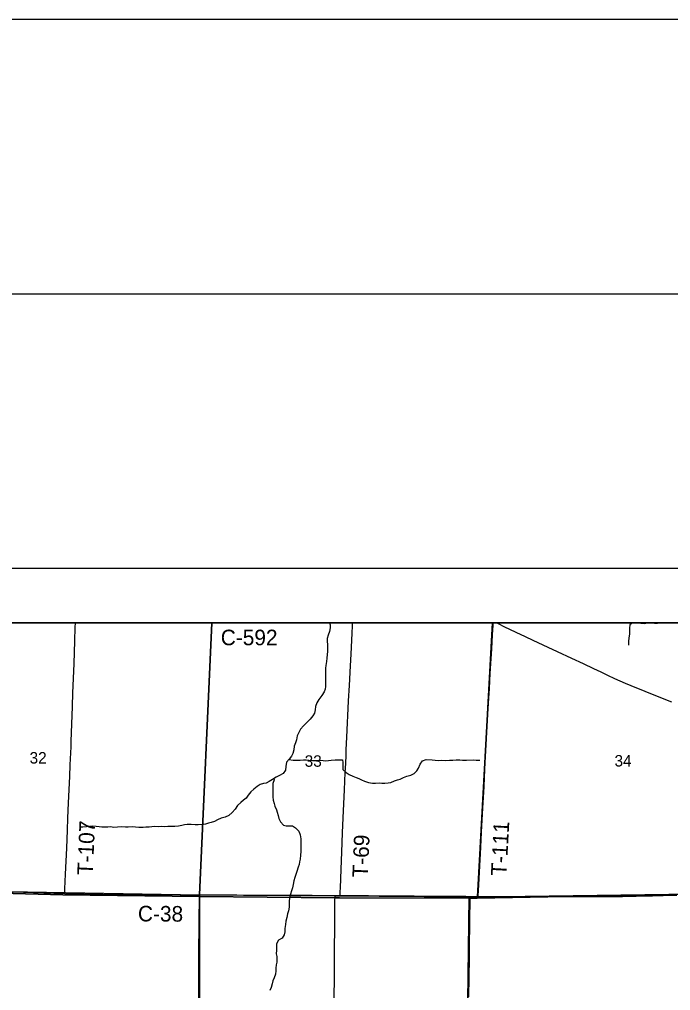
# Model space of a CAD drawing. Extents: x 0 to 34, y 0 to 22.
# Drawn here: x 3.165 to 4.352, y 20.23 to 22 of the extents above; entities that cross this region are included whole.
import ezdxf

# ---------------------------------------------------------------- set-up
doc = ezdxf.new("R2010")
doc.units = 0
for name, color, linetype in [('GM_X_County', 7, 'Continuous'), ('GM_X_County_Road', 7, 'Continuous'), ('GM_X_County_Road_Text', 7, 'Continuous'), ('GM_X_Minor_River', 7, 'Continuous'), ('GM_X_Section', 7, 'Continuous'), ('GM_X_Section_Text', 7, 'Continuous'), ('GM_X_Township', 7, 'Continuous'), ('GM_X_Township_Road', 7, 'Continuous'), ('GM_X_Township_Road_Text', 7, 'Continuous'), ('SH_Border', 7, 'Continuous'), ('SH_Cut_Line', 7, 'Continuous'), ('SH_Data', 7, 'Continuous')]:
    doc.layers.add(name, color=color, linetype=linetype)

msp = doc.modelspace()

# ---------------------------------------------------------------- linework, layer by layer
at = {"layer": 'GM_X_County'}
msp.add_lwpolyline([(9.4, 14.3965), (9.4, 20.9), (2.6, 20.9), (2.6, 14.4092)], dxfattribs=at)
at = {"layer": 'GM_X_County_Road'}
for points in [[(4.3542, 20.7556), (4.3253, 20.7671), (4.3057, 20.7749), (4.2803, 20.7852), (4.2695, 20.7898), (4.2504, 20.7983), (4.2375, 20.8044), (4.2254, 20.8101), (4.2122, 20.8162), (4.193, 20.8252), (4.1717, 20.8353), (4.146, 20.8472), (4.1291, 20.8551), (4.1013, 20.8682), (4.0872, 20.8748), (4.0703, 20.8827), (4.0487, 20.893), (4.0393, 20.8974), (4.0342, 20.9)], [(2.9957, 20.4134), (3.0058, 20.4131), (3.0244, 20.4127), (3.0421, 20.4123), (3.0896, 20.411), (3.1148, 20.4104), (3.1729, 20.4089), (3.2279, 20.4074), (3.2478, 20.4069)], [(3.2478, 20.4069), (3.2832, 20.4061), (3.3174, 20.4057), (3.3622, 20.4052), (3.3858, 20.405), (3.4175, 20.4048), (3.4461, 20.4047), (3.4585, 20.4046), (3.4744, 20.4046), (3.4932, 20.4045)], [(3.4932, 20.4045), (3.5045, 20.4044), (3.5303, 20.4042), (3.5481, 20.4041), (3.5617, 20.404), (3.5735, 20.4039), (3.585, 20.4038), (3.6077, 20.4038), (3.6494, 20.4036), (3.6758, 20.4034), (3.6985, 20.4034), (3.7094, 20.4033), (3.7196, 20.4032), (3.728, 20.4031), (3.7404, 20.4031)], [(3.7404, 20.4031), (3.7499, 20.4031)], [(3.7499, 20.4031), (3.7622, 20.4031), (3.7889, 20.4028), (3.8014, 20.4028), (3.8194, 20.4026), (3.8495, 20.4025), (3.8663, 20.4023), (3.8846, 20.4022), (3.9083, 20.4021), (3.9543, 20.4017), (3.9785, 20.4016), (3.9866, 20.4015)], [(3.9866, 20.4015), (3.9928, 20.4015), (4.001, 20.4014)], [(4.001, 20.4014), (4.0028, 20.4014), (4.0152, 20.4014), (4.0435, 20.4013), (4.0531, 20.4012), (4.0649, 20.4012), (4.0848, 20.4011), (4.0917, 20.4011), (4.1041, 20.4013), (4.1181, 20.4012), (4.1321, 20.4012), (4.1442, 20.4012), (4.1647, 20.4011), (4.1818, 20.4012), (4.1908, 20.4012), (4.2007, 20.4013), (4.2259, 20.4014), (4.2645, 20.4015), (4.2735, 20.4017), (4.289, 20.4019), (4.3192, 20.4026), (4.3381, 20.4032), (4.3633, 20.4039)]]:
    msp.add_lwpolyline(points, dxfattribs=at)
at = {"layer": 'GM_X_Minor_River'}
for points in [[(3.7303, 20.9), (3.7313, 20.8965), (3.7314, 20.8908), (3.7304, 20.8845), (3.7278, 20.8779), (3.7262, 20.8713), (3.726, 20.8658), (3.7264, 20.8607), (3.7269, 20.854), (3.7265, 20.848), (3.7261, 20.8423), (3.7255, 20.8356), (3.7247, 20.8294), (3.7234, 20.8224), (3.723, 20.8174), (3.7229, 20.8121), (3.7231, 20.8055), (3.7231, 20.8002), (3.7232, 20.7954), (3.723, 20.7905), (3.723, 20.7839), (3.7224, 20.7791), (3.7207, 20.7742), (3.7163, 20.7674), (3.7111, 20.7602), (3.7075, 20.754), (3.705, 20.7474), (3.7044, 20.7417), (3.7029, 20.7356), (3.7002, 20.7307), (3.6949, 20.7245), (3.6892, 20.7184), (3.6829, 20.7126), (3.6777, 20.7063), (3.6747, 20.7001), (3.6714, 20.694), (3.6699, 20.6868), (3.6684, 20.6812), (3.6661, 20.6753), (3.6653, 20.6688), (3.6635, 20.6622), (3.661, 20.6573), (3.6567, 20.6518), (3.6519, 20.646), (3.6509, 20.6382), (3.6499, 20.6317), (3.6457, 20.6253), (3.6395, 20.6217), (3.6332, 20.6185), (3.6262, 20.6144), (3.6203, 20.6106), (3.615, 20.6078), (3.6102, 20.6073), (3.604, 20.6054), (3.5985, 20.602), (3.5922, 20.5969), (3.5871, 20.5922), (3.5823, 20.5858), (3.5785, 20.5807), (3.5735, 20.5767), (3.5686, 20.5726), (3.5629, 20.5669), (3.5583, 20.5605), (3.553, 20.5542), (3.5469, 20.5488), (3.54, 20.5456), (3.5332, 20.5443), (3.5264, 20.5411), (3.5209, 20.5379), (3.5148, 20.536), (3.5099, 20.5349), (3.5046, 20.5332), (3.4983, 20.5327), (3.4913, 20.532), (3.4854, 20.5318), (3.478, 20.5326), (3.4712, 20.5326), (3.4661, 20.5319), (3.4612, 20.5308), (3.4553, 20.5295), (3.4483, 20.5288), (3.4426, 20.529), (3.436, 20.529), (3.4299, 20.5285), (3.4248, 20.5287), (3.4183, 20.5285), (3.4113, 20.5287), (3.4018, 20.5276), (3.3954, 20.5275), (3.3907, 20.5269), (3.3829, 20.527), (3.377, 20.5276), (3.3706, 20.5282), (3.3634, 20.5278), (3.3584, 20.5277)], [(4.2827, 20.9), (4.2777, 20.8965), (4.2769, 20.8905), (4.2773, 20.8844), (4.277, 20.8793), (4.2759, 20.8725), (4.2752, 20.8658), (4.2752, 20.8592)], [(4.3289, 20.9), (4.3277, 20.8991), (4.3228, 20.8991), (4.3158, 20.8999), (4.3096, 20.8992), (4.3044, 20.8985), (4.2976, 20.8989), (4.2902, 20.8997), (4.285, 20.9)], [(3.6563, 20.6514), (3.6565, 20.6512), (3.6639, 20.6499), (3.6701, 20.6497), (3.6766, 20.6498), (3.683, 20.6505), (3.6877, 20.6505), (3.6928, 20.6499), (3.6991, 20.6491), (3.7061, 20.6491), (3.711, 20.6498), (3.7188, 20.6489), (3.7237, 20.6488), (3.7288, 20.6494), (3.7336, 20.6497), (3.7406, 20.6503), (3.7476, 20.6506), (3.7541, 20.6502), (3.7546, 20.6453), (3.7544, 20.639), (3.7547, 20.6326), (3.7604, 20.627), (3.7661, 20.6236), (3.7727, 20.6207), (3.7787, 20.6182), (3.784, 20.6161), (3.7889, 20.6138), (3.7939, 20.6113), (3.8011, 20.6088), (3.8086, 20.6078), (3.8141, 20.6078), (3.8206, 20.6085), (3.8259, 20.6081), (3.8314, 20.6079), (3.8371, 20.6083), (3.8418, 20.609), (3.8486, 20.612), (3.8543, 20.6137), (3.8591, 20.615), (3.865, 20.618), (3.8714, 20.6206), (3.8786, 20.6223), (3.8849, 20.6257), (3.8896, 20.6304), (3.8925, 20.6353), (3.8956, 20.6423), (3.9, 20.6488), (3.9064, 20.6508), (3.9176, 20.6501)], [(3.9176, 20.6501), (3.9284, 20.649), (3.9352, 20.6495), (3.9424, 20.6491), (3.9489, 20.6495), (3.9553, 20.65), (3.9612, 20.6503), (3.9678, 20.6501), (3.9727, 20.6497), (3.9797, 20.6498), (3.993, 20.6501), (3.9979, 20.6499), (4.0042, 20.6495)], [(3.629, 20.616), (3.6296, 20.6142), (3.6269, 20.6072), (3.6273, 20.6007), (3.6272, 20.5945), (3.6268, 20.589), (3.627, 20.5827), (3.6275, 20.5768), (3.6292, 20.5709), (3.6309, 20.5662), (3.6335, 20.5595), (3.6352, 20.5548), (3.6369, 20.5487), (3.638, 20.5436), (3.641, 20.5371), (3.6465, 20.5314), (3.6514, 20.5299), (3.6561, 20.5302), (3.6631, 20.5298), (3.6682, 20.5262), (3.6743, 20.5203), (3.6771, 20.5136), (3.6778, 20.5064), (3.6778, 20.4996), (3.678, 20.4931), (3.6783, 20.4882), (3.6783, 20.4835), (3.6777, 20.4766), (3.6771, 20.4696), (3.6759, 20.4647), (3.675, 20.4596), (3.6734, 20.4545), (3.6706, 20.4469), (3.6688, 20.4414), (3.6669, 20.4359), (3.6656, 20.4298), (3.664, 20.4234), (3.6627, 20.417), (3.6609, 20.4115), (3.6592, 20.4056), (3.6577, 20.3988), (3.6567, 20.3921), (3.6568, 20.3872), (3.6566, 20.3819), (3.6558, 20.3751), (3.6539, 20.3694), (3.6524, 20.3631), (3.651, 20.3565), (3.6499, 20.3502), (3.6489, 20.3427), (3.6487, 20.3368), (3.6477, 20.3315), (3.6439, 20.3252), (3.6372, 20.3215), (3.634, 20.3148), (3.6338, 20.3092), (3.6336, 20.3037), (3.6333, 20.2968), (3.6341, 20.2917), (3.6344, 20.287), (3.6342, 20.2818), (3.6333, 20.2765), (3.6323, 20.2707), (3.6323, 20.2655), (3.6317, 20.2599), (3.6292, 20.2532), (3.6273, 20.2477), (3.6261, 20.242), (3.6238, 20.2352), (3.6219, 20.2297)], [(3.3584, 20.5277), (3.3512, 20.5281), (3.3442, 20.5275), (3.3376, 20.527), (3.3315, 20.528), (3.3266, 20.5274), (3.3215, 20.5275), (3.3152, 20.5279), (3.3103, 20.5283), (3.305, 20.5291), (3.2984, 20.5293), (3.2874, 20.5282), (3.2809, 20.5277), (3.2745, 20.5279)]]:
    msp.add_lwpolyline(points, dxfattribs=at)
at = {"layer": 'GM_X_Section'}
for p, q in [((3.5157, 20.9), (3.0175, 20.9)), ((4.0273, 20.9), (3.5157, 20.9)), ((4.5309, 20.9), (4.0273, 20.9))]:
    msp.add_line(p, q, dxfattribs=at)
for points in [[(3.0175, 20.9), (2.9944, 20.4131), (3.0048, 20.4128), (3.4935, 20.4042), (3.5157, 20.9)], [(3.5157, 20.9), (3.4935, 20.4042), (3.9846, 20.4004), (4.0003, 20.4004), (4.0273, 20.9)], [(4.0273, 20.9), (4.0003, 20.4004), (4.4795, 20.4072), (4.5051, 20.4076), (4.5309, 20.9)]]:
    msp.add_lwpolyline(points, dxfattribs=at)
for points in [[(3.0048, 20.4128), (3.4935, 20.4042), (3.4937, 19.9171), (2.9961, 19.9305)], [(3.9846, 20.4004), (3.9787, 19.9246), (3.4937, 19.9171), (3.4935, 20.4042)], [(3.9846, 20.4004), (4.0003, 20.4004), (4.4795, 20.4072), (4.4798, 19.9188), (3.9787, 19.9246)]]:
    msp.add_lwpolyline(points, close=True, dxfattribs=at)
at = {"layer": 'GM_X_Township'}
for points in [[(5.5392, 20.9), (2.6, 20.9), (2.6, 20.4221)], [(2.6, 20.4221), (2.9952, 20.4112), (3.2446, 20.4043), (3.4937, 20.4014), (3.7398, 20.3991), (3.7483, 20.3991), (3.9866, 20.3982), (3.9992, 20.3981), (4.4815, 20.4071), (4.5066, 20.4075), (4.771, 20.4128), (5.041, 20.4202), (5.5101, 20.4256), (5.5392, 20.9)], [(4.4815, 20.4071), (3.9992, 20.3981), (3.9866, 20.3982), (3.7483, 20.3991), (3.7398, 20.3991), (3.4937, 20.4014), (3.2446, 20.4043), (2.9952, 20.4112), (2.6, 20.4221)]]:
    msp.add_lwpolyline(points, dxfattribs=at)
at = {"layer": 'GM_X_Township_Road'}
for points in [[(3.2478, 20.4069), (3.2479, 20.4077), (3.2482, 20.4154), (3.2493, 20.4418), (3.2514, 20.4893), (3.2528, 20.5222), (3.2538, 20.5443), (3.255, 20.5722), (3.2571, 20.6201), (3.258, 20.6412), (3.2594, 20.6738), (3.2597, 20.6837), (3.262, 20.7474), (3.2628, 20.7723), (3.2648, 20.8254), (3.2662, 20.8673), (3.2671, 20.8913), (3.2674, 20.9)], [(3.7499, 20.4031), (3.7499, 20.4041), (3.75, 20.4103), (3.7501, 20.4162), (3.7515, 20.4513), (3.7528, 20.4823), (3.7541, 20.5174), (3.7553, 20.5448), (3.7577, 20.5954), (3.7591, 20.627), (3.7599, 20.6438), (3.7606, 20.659), (3.761, 20.6689), (3.762, 20.6919), (3.7626, 20.7043), (3.7633, 20.7183), (3.7638, 20.7304), (3.7652, 20.758), (3.7666, 20.7857), (3.7685, 20.8217), (3.7696, 20.8431), (3.7715, 20.881), (3.772, 20.8949), (3.7721, 20.9)], [(4.001, 20.4014), (4.0011, 20.4026), (4.0022, 20.4221), (4.0029, 20.4342), (4.0059, 20.491), (4.0075, 20.5186), (4.0098, 20.5621), (4.011, 20.5817), (4.0119, 20.6009), (4.0127, 20.618), (4.0135, 20.6323), (4.0142, 20.6478), (4.0154, 20.6714), (4.0167, 20.6947), (4.0207, 20.763), (4.0218, 20.7803), (4.0225, 20.7943), (4.0233, 20.8077), (4.0259, 20.8527), (4.0274, 20.8781), (4.0285, 20.8955), (4.0288, 20.9)], [(3.492, 20.2158), (3.4921, 20.2388), (3.4921, 20.2615), (3.4923, 20.2821), (3.4924, 20.301), (3.4925, 20.3163), (3.4926, 20.3331), (3.4928, 20.3529), (3.493, 20.3713), (3.4932, 20.3858), (3.4932, 20.3942), (3.4932, 20.4012), (3.4932, 20.4045)], [(3.7378, 19.9202), (3.7379, 19.9444), (3.738, 19.9705), (3.7381, 19.9876), (3.7382, 20.0302), (3.7383, 20.0566), (3.7384, 20.0672), (3.7386, 20.0917), (3.7387, 20.1113), (3.7387, 20.1266), (3.7386, 20.1465), (3.7388, 20.1679), (3.7388, 20.1881), (3.739, 20.2223), (3.7392, 20.2481), (3.7395, 20.2801), (3.7397, 20.295), (3.7397, 20.3137), (3.7398, 20.3364), (3.74, 20.3709), (3.7402, 20.3939), (3.7404, 20.401), (3.7404, 20.4031)], [(3.9844, 20.2182), (3.9845, 20.2338), (3.9846, 20.2384), (3.9846, 20.2394), (3.9847, 20.2425), (3.9848, 20.2471), (3.9848, 20.248), (3.9849, 20.2511), (3.985, 20.2577), (3.9851, 20.2608), (3.9851, 20.2689), (3.9852, 20.2735), (3.9852, 20.281), (3.9853, 20.2856), (3.9853, 20.2878), (3.9854, 20.2971), (3.9855, 20.2999), (3.9856, 20.3096), (3.9856, 20.3177), (3.9857, 20.3211), (3.9857, 20.3295), (3.9858, 20.3332), (3.9859, 20.3391), (3.9861, 20.3587), (3.9863, 20.3714), (3.9865, 20.3829), (3.9866, 20.3851), (3.9867, 20.3929), (3.9866, 20.3976), (3.9866, 20.4015)]]:
    msp.add_lwpolyline(points, dxfattribs=at)
at = {"layer": 'SH_Border'}
msp.add_lwpolyline([(2, 21.5), (33.5, 21.5), (33.5, 0.5), (2, 0.5)], close=True, dxfattribs=at)
at = {"layer": 'SH_Cut_Line'}
msp.add_lwpolyline([(0, 0), (34, 0), (34, 22), (0, 22)], close=True, dxfattribs=at)
at = {"layer": 'SH_Data'}
for p, q in [((2.5, 21), (9.5, 21)), ((2.6, 20.9), (9.4, 20.9))]:
    msp.add_line(p, q, dxfattribs=at)

# ---------------------------------------------------------------- texts
at = {"layer": 'GM_X_County_Road_Text'}
for s, rotation, p in [('C-592', 0, (3.5322, 20.8592)), ('C-38', 359.6548, (3.3812, 20.3559))]:
    msp.add_text(s, height=0.02841, rotation=rotation, dxfattribs=at).set_placement(p)
at = {"layer": 'GM_X_Section_Text'}
for s, p in [('32', (3.1838, 20.6436)), ('33', (3.6851, 20.6377)), ('34', (4.2497, 20.6382))]:
    msp.add_text(s, height=0.02093, rotation=0, dxfattribs=at).set_placement(p)
at = {"layer": 'GM_X_Township_Road_Text'}
for s, rotation, p in [('T-107', 87.4745, (3.2989, 20.4397)), ('T-111', 86.9137, (4.0527, 20.4384)), ('T-69', 87.5581, (3.8002, 20.4354))]:
    msp.add_text(s, height=0.02841, rotation=rotation, dxfattribs=at).set_placement(p)

doc.saveas('drawing.dxf')
